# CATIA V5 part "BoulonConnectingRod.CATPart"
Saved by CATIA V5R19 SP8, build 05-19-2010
Part number: BoulonConnectingRod
Bounding box of the stored display mesh (mm): x -25.5 to 21.5, y 672 to 688, z 492 to 508
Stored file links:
  G:\EU_thinkMotion\CFAO_2010\MMS_groupe3\MMS_groupe3\A reprendre\fovide\fovide\BoulonConnectingRod.CATPart
  C:\Users\Rodger\Desktop\Part11.CATPart
  G:\EU_thinkMotion\CFAO_2010\MMS_groupe3\MMS_groupe3\A reprendre\fovide\fovide\fovide.CATProduct
  G:\EU_thinkMotion\CFAO_2010\MMS_groupe3\MMS_groupe3\A reprendre\fovide\fovide\Connecting Rod 37.CATPart
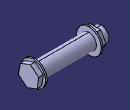
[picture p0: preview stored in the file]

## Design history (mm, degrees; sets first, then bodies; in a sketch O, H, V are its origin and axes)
Parameters
  Diametre = 10 mm
  Longueur = 35 mm
Set1
  DatumSurface1: linked copy from another document
  Point1: linked copy from another document
Body1 (main body)
Body2
  Sketch1 on DatumSurface1, origin (17.5, 0, 17.5), H (0, 0, -1), V (0, 1, 0)
    circle A1 centre (-482.5, 680) radius 8
    point P1 (-482.5, 680)
    reference projected point E1 (-482.5, 680) from Point1
    radius A1 = 8 {= Diametre *8/10}
    coincidence: P1 E1
  Pad1: profile Sketch1, direction (1, 0, 0), length 1
  Sketch2 on end face of Pad1, origin (18.5, 0, 19.5), H (0, 0, -1), V (0, 1, 0)
    point P1 (-480.5, 680)
    point P2 (-478.0061, 673.4593)
    point P3 (-473.5887, 678.8894)
    point P4 (-476.0825, 685.4301)
    point P5 (-482.9939, 686.5407)
    point P6 (-487.4113, 681.1106)
    point P7 (-484.9175, 674.5699)
    point P8 (-475.7974, 676.1744)
    line L1 (-478.0061, 673.4593) -> (-473.5887, 678.8894)
    line L2 (-473.5887, 678.8894) -> (-476.0825, 685.4301)
    line L3 (-476.0825, 685.4301) -> (-482.9939, 686.5407)
    line L4 (-482.9939, 686.5407) -> (-487.4113, 681.1106)
    line L5 (-487.4113, 681.1106) -> (-484.9175, 674.5699)
    line L6 (-484.9175, 674.5699) -> (-478.0061, 673.4593)
    construction line L7 (-480.5, 680) -> (-475.7974, 676.1744)
    construction circle A1 centre (-480.5, 680) radius 7
    construction arc A2 centre (-487.4113, 681.1106) radius 7 from (-482.9939, 686.5407) to (-484.9175, 674.5699) cw
    construction arc A3 centre (-473.5887, 678.8894) radius 7 from (-476.0825, 685.4301) to (-478.0061, 673.4593) ccw
    reference projected point E1 (-480.5, 680) from Point1
    radius A1 = 7 {= Diametre *7/10}
    coincidence: A1 P2, A1 P3, A1 P4, A1 P5, A1 P6, A1 P7, A2 P1, A3 P1, P1 E1
    midpoint: P8 L1
    parallelism: L1 L4
  Pad2: profile Sketch2, direction (1, 0, 0), length 3
  Sketch3 on start face of Pad1, origin (17.5, 0, 17.5), H (0, 0, -1), V (0, -1, 0)
    circle A1 centre (-482.5, -680) radius 5
    point P1 (-482.5, -680)
    reference projected point E1 (-482.5, -680) from Point1
    radius A1 = 5 {= Diametre /2}
    coincidence: P1 E1
  Pad3: profile Sketch3, direction (-1, 0, 0), length 35 {= Longueur}
  Sketch4 on end face of Pad3, origin (-17.5, 0, -62.5), H (0, 0, -1), V (0, -1, 0)
    circle A1 centre (-562.5, -680) radius 8
    point P1 (-562.5, -680)
    reference projected point E1 (-562.5, -680) from Point1
    radius A1 = 8 {= Diametre *8/10}
    coincidence: P1 E1
  Pad4: profile Sketch4, direction (-1, 0, 0), length 1
  Sketch5 on end face of Pad4, origin (-18.5, 0, -64.5), H (0, 0, -1), V (0, -1, 0)
    point P1 (-564.5, -680)
    point P2 (-564.5478, -686.9998)
    point P3 (-558.4619, -683.5413)
    point P4 (-558.4141, -676.5415)
    point P5 (-564.4522, -673.0002)
    point P6 (-570.5381, -676.4587)
    point P7 (-570.5859, -683.4585)
    point P8 (-561.5048, -685.2706)
    line L1 (-564.5478, -686.9998) -> (-558.4619, -683.5413)
    line L2 (-558.4619, -683.5413) -> (-558.4141, -676.5415)
    line L3 (-558.4141, -676.5415) -> (-564.4522, -673.0002)
    line L4 (-564.4522, -673.0002) -> (-570.5381, -676.4587)
    line L5 (-570.5381, -676.4587) -> (-570.5859, -683.4585)
    line L6 (-570.5859, -683.4585) -> (-564.5478, -686.9998)
    construction line L7 (-564.5, -680) -> (-561.5048, -685.2706)
    construction circle A1 centre (-564.5, -680) radius 7
    construction arc A2 centre (-570.5381, -676.4587) radius 7 from (-564.4522, -673.0002) to (-570.5859, -683.4585) cw
    construction arc A3 centre (-558.4619, -683.5413) radius 7 from (-558.4141, -676.5415) to (-564.5478, -686.9998) ccw
    reference projected point E1 (-564.5, -680) from Point1
    radius A1 = 7 {= Diametre *7/10}
    coincidence: A1 P2, A1 P3, A1 P4, A1 P5, A1 P6, A1 P7, A2 P1, A3 P1, P1 E1
    midpoint: P8 L1
    parallelism: L1 L4
  Pad5: profile Sketch5, direction (-1, 0, 0), length 3
  Sketch6 on end face of Pad5, origin (-21.5, 0, -70.5), H (0, 0, -1), V (0, -1, 0)
    circle A1 centre (-570.5, -680) radius 5
    point P1 (-570.5, -680)
    reference projected point E1 (-570.5, -680) from Point1
    radius A1 = 5 {= Diametre /2}
    coincidence: P1 E1
  Pad6: profile Sketch6, direction (-1, 0, 0), length 4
